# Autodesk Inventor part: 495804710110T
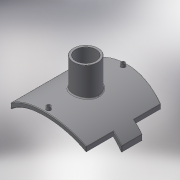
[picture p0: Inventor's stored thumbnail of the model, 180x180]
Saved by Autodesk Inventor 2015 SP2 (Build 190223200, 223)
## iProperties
Created: 2017-10
Part Number: 495804710110T
Material: Generic
Description: PLASSON BRANCH SADDLE 450-800X110
Document SubType Name: Modeling
Designer: KIM
Density: 1 g/cm^3
Appearance: Default
Author: KIM
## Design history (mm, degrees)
derived "495804 (SECOND).ipt"
feature "Solid1::495804 (SECOND).ipt"
tag "TaggingFeature1"
body "Solid1"
other parameters: "d1" = 15, "d2" = 283.5, "d4" = 0, "d5" = 315, "d6" = 75, "d7" = 0, "d8" = 135, "d10" = 0, "d11" = 4, "d12" = 425.6, "d13" = 14, "d14" = 135, "d16" = 5 deg, "d18" = 4, "d19" = 14, "d20" = 0, "d21" = 3, "d22" = 0, "d25" = 16, "d26" = 88, "d28" = 0, "d29" = 9.6, "d31" = 0, "d32" = 31.5, "d33" = 0, "d34" = 8, "d35" = 1.6, "B_" = 315, "H_" = 105, "x_" = 15, "D_" = 16
